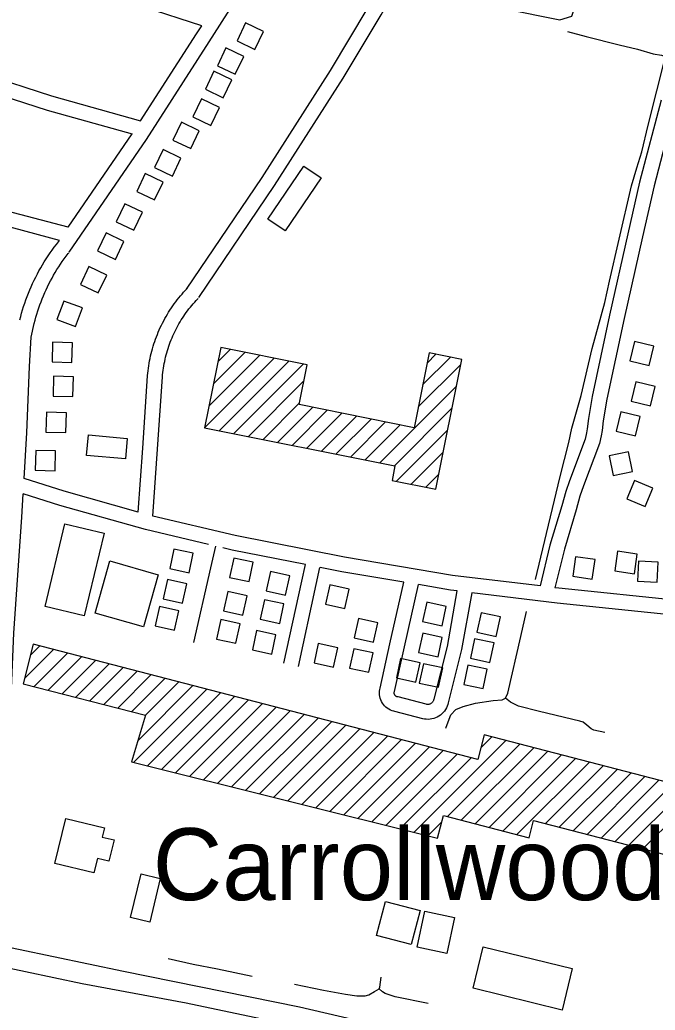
# Model space of a CAD drawing. Extents: x 3540316 to 3578335, y 553172 to 578787.
# Drawn here: x 3545660 to 3546942, y 572760 to 574758 of the extents above; entities that cross this region are included whole.
import ezdxf

# ---------------------------------------------------------------- set-up
doc = ezdxf.new("R2010")
doc.units = 0
for name, color, linetype in [('V-BLDG-OTLN', 7, 'Continuous'), ('V-ROAD-CNTR', 7, 'Continuous'), ('V-TOPO-GNAM-IDEN', 7, 'Continuous'), ('V-TOPO-SHOR', 7, 'Continuous')]:
    doc.layers.add(name, color=color, linetype=linetype)

msp = doc.modelspace()

# ---------------------------------------------------------------- linework, layer by layer
at = {"layer": 'V-BLDG-OTLN'}
for p, q in [((3546042, 573979.6), (3546144.2, 574081.8)), ((3546050.9, 574023.9), (3546114.7, 574087.7)), ((3546059.8, 574068.1), (3546085.3, 574093.6)), ((3546481.9, 574066), (3546499.5, 574083.6)), ((3546033.1, 573935.4), (3546173.6, 574075.9)), ((3546062.6, 573929.5), (3546203.1, 574070)), ((3546092, 573923.6), (3546232.5, 574064.1)), ((3546464.2, 573977.5), (3546549.8, 574063.1)), ((3546473, 574021.8), (3546528.9, 574077.6)), ((3546121.5, 573917.7), (3546233.6, 574029.8)), ((3546386.5, 573864.5), (3546540.9, 574018.9)), ((3546150.9, 573911.8), (3546224.7, 573985.5)), ((3546180.4, 573905.9), (3546251, 573976.5)), ((3546209.8, 573899.9), (3546280.5, 573970.6)), ((3546239.3, 573894), (3546309.9, 573964.7)), ((3546415.9, 573858.6), (3546532, 573974.7)), ((3546268.7, 573888.1), (3546339.4, 573958.8)), ((3546298.1, 573882.2), (3546368.8, 573952.9)), ((3546327.6, 573876.3), (3546398.3, 573947)), ((3546357, 573870.4), (3546427.7, 573941.1)), ((3546420.2, 573827.5), (3546523.1, 573930.4)), ((3546449.7, 573821.6), (3546514.3, 573886.2)), ((3546479.1, 573815.7), (3546505.4, 573842)), ((3545670, 573429.6), (3545728.4, 573488)), ((3545681.9, 573476.9), (3545700.3, 573495.3)), ((3545689.2, 573413.5), (3545756.4, 573480.7)), ((3545717.3, 573406.2), (3545784.5, 573473.5)), ((3545745.4, 573398.9), (3545812.6, 573466.2)), ((3545773.4, 573391.7), (3545840.7, 573458.9)), ((3545801.5, 573384.4), (3545868.8, 573451.6)), ((3545829.6, 573377.1), (3545896.9, 573444.4)), ((3545857.7, 573369.8), (3545924.9, 573437.1)), ((3545885.8, 573362.6), (3545953, 573429.8)), ((3545913.9, 573355.3), (3545981.1, 573422.6)), ((3545889.5, 573260.2), (3546037.3, 573408)), ((3545898.7, 573304.8), (3546009.2, 573415.3)), ((3545917.8, 573253.1), (3546065.4, 573400.7)), ((3545946.1, 573246.1), (3546093.4, 573393.5)), ((3545974.4, 573239), (3546121.5, 573386.2)), ((3546002.7, 573232), (3546149.6, 573378.9)), ((3546030.9, 573224.9), (3546177.7, 573371.7)), ((3546059.2, 573217.8), (3546205.8, 573364.4)), ((3546087.5, 573210.8), (3546233.9, 573357.1)), ((3546115.8, 573203.7), (3546261.9, 573349.8)), ((3546144.1, 573196.7), (3546290, 573342.6)), ((3546172.4, 573189.6), (3546318.1, 573335.3)), ((3546200.7, 573182.6), (3546346.2, 573328)), ((3546229, 573175.5), (3546374.3, 573320.7)), ((3546257.3, 573168.4), (3546402.4, 573313.5)), ((3546285.6, 573161.4), (3546430.4, 573306.2)), ((3546455.4, 573119), (3546640.8, 573304.4)), ((3546590.7, 573289.7), (3546612.7, 573311.7)), ((3546313.9, 573154.3), (3546458.5, 573298.9)), ((3546342.2, 573147.3), (3546486.6, 573291.7)), ((3546370.5, 573140.2), (3546514.7, 573284.4)), ((3546522.8, 573151.1), (3546668.9, 573297.2)), ((3546550.9, 573143.8), (3546697, 573289.9)), ((3546579, 573136.5), (3546725.1, 573282.6)), ((3546398.8, 573133.1), (3546542.8, 573277.1)), ((3546427.1, 573126.1), (3546570.9, 573269.8)), ((3546607.1, 573129.3), (3546753.1, 573275.3)), ((3546635.2, 573122), (3546781.2, 573268.1)), ((3546663.3, 573114.8), (3546809.3, 573260.8)), ((3546720.5, 573136.7), (3546837.4, 573253.5)), ((3546748.6, 573129.4), (3546865.5, 573246.3)), ((3546776.7, 573122.1), (3546893.5, 573239)), ((3546804.8, 573114.9), (3546921.6, 573231.7)), ((3546832.9, 573107.6), (3546949.7, 573224.4)), ((3546861, 573100.3), (3546977.8, 573217.2)), ((3546889.1, 573093.1), (3547007, 573211.1)), ((3546917.2, 573085.8), (3547035.1, 573203.8)), ((3546483.7, 573112), (3546511.3, 573139.6))]:
    msp.add_line(p, q, dxfattribs=at)
for points in [[(3546115.9, 574752), (3546098.6, 574715.9), (3546134.7, 574698.6), (3546152, 574734.7)], [(3546076.1, 574701.9), (3546058.8, 574665.8), (3546094.9, 574648.5), (3546112.2, 574684.6)], [(3546052, 574654.5), (3546034.7, 574618.4), (3546070.8, 574601.1), (3546088.1, 574637.2)], [(3546026.7, 574598.8), (3546009.4, 574562.7), (3546045.5, 574545.4), (3546062.8, 574581.5)], [(3545986.3, 574551.8), (3545969.1, 574515.8), (3546005.1, 574498.5), (3546022.4, 574534.6)], [(3545949.3, 574496.4), (3545932, 574460.4), (3545968.1, 574443.1), (3545985.4, 574479.2)], [(3546160.9, 574356.5), (3546233.4, 574463), (3546268.1, 574439.4), (3546195.6, 574332.9)], [(3545913.2, 574448.3), (3545896, 574412.2), (3545932, 574394.9), (3545949.3, 574431)], [(3545871.8, 574387.2), (3545854.6, 574351.1), (3545890.6, 574333.9), (3545907.9, 574370)], [(3545834.3, 574328.4), (3545817.1, 574292.3), (3545853.1, 574275), (3545870.4, 574311.1)], [(3545799.8, 574260.7), (3545782.6, 574224.6), (3545818.6, 574207.4), (3545835.9, 574243.5)], [(3545735, 574153.5), (3545772.6, 574139.6), (3545786.4, 574177.1), (3545748.9, 574191)], [(3545726.3, 574108), (3545725.3, 574068.1), (3545765.3, 574067), (3545766.3, 574107)], [(3546900.2, 574109.4), (3546890.8, 574070.6), (3546929.7, 574061.2), (3546939.1, 574100)], [(3546033.1, 573935.4), (3546417.2, 573858.3), (3546411.4, 573829.3), (3546499.3, 573811.6), (3546551.8, 574073.1), (3546486, 574086.3), (3546455.7, 573935.5), (3546224, 573982), (3546240.1, 574062.5), (3546065.7, 574097.6)], [(3545728.4, 574039.2), (3545727.4, 573999.2), (3545767.4, 573998.2), (3545768.4, 574038.2)], [(3546903.2, 574028.2), (3546893.8, 573989.3), (3546932.7, 573979.9), (3546942.1, 574018.8)], [(3545714.1, 573966.7), (3545713, 573926.7), (3545753, 573925.7), (3545754.1, 573965.7)], [(3546872.7, 573967.3), (3546863.3, 573928.5), (3546902.2, 573919), (3546911.6, 573957.9)], [(3545798.6, 573920.8), (3545877.1, 573913.9), (3545873.4, 573872.4), (3545794.9, 573879.4)], [(3545692.4, 573889.5), (3545691.4, 573849.5), (3545731.4, 573848.5), (3545732.4, 573888.5)], [(3546896.6, 573847.4), (3546888.6, 573886.5), (3546849.4, 573878.5), (3546857.5, 573839.3)], [(3546885, 573791.7), (3546922, 573776.6), (3546937.1, 573813.6), (3546900.1, 573828.7)], [(3545711.4, 573574.9), (3545751.2, 573741.3), (3545830.1, 573722.4), (3545790.2, 573556)], [(3545962.7, 573651.5), (3546001.8, 573643), (3546010.3, 573682.1), (3545971.3, 573690.6)], [(3546900.1, 573640.8), (3546905.8, 573680.4), (3546866.2, 573686.1), (3546860.5, 573646.5)], [(3545812.2, 573561.5), (3545842, 573666.6), (3545939.4, 573638.9), (3545909.5, 573533.8)], [(3546083.6, 573633.4), (3546122.7, 573624.9), (3546131.2, 573664), (3546092.1, 573672.5)], [(3546815.3, 573630), (3546821, 573669.6), (3546781.4, 573675.3), (3546775.7, 573635.8)], [(3546948.3, 573664), (3546908.4, 573666.2), (3546906.2, 573626.2), (3546946.1, 573624.1)], [(3546157.4, 573606.1), (3546196.5, 573597.6), (3546205.1, 573636.6), (3546166, 573645.2)], [(3545949.5, 573590.2), (3545988.6, 573581.7), (3545997.2, 573620.8), (3545958.1, 573629.3)], [(3546071.1, 573566), (3546110.1, 573557.5), (3546118.7, 573596.5), (3546079.6, 573605.1)], [(3546276.9, 573579.5), (3546315.9, 573570.9), (3546324.5, 573610), (3546285.4, 573618.5)], [(3546145.5, 573549.4), (3546184.6, 573540.8), (3546193.1, 573579.9), (3546154.1, 573588.4)], [(3546473, 573544.5), (3546512.1, 573535.9), (3546520.6, 573575), (3546481.5, 573583.5)], [(3545933.6, 573535.8), (3545972.6, 573527.2), (3545981.2, 573566.3), (3545942.1, 573574.9)], [(3546582.5, 573523.2), (3546621.5, 573514.6), (3546630.1, 573553.7), (3546591, 573562.3)], [(3546057.3, 573509.2), (3546096.3, 573500.7), (3546104.9, 573539.7), (3546065.8, 573548.3)], [(3546335, 573511.6), (3546374.1, 573503), (3546382.6, 573542.1), (3546343.6, 573550.7)], [(3546129.4, 573487.2), (3546168.5, 573478.6), (3546177.1, 573517.7), (3546138, 573526.3)], [(3546464.9, 573481.7), (3546504, 573473.1), (3546512.5, 573512.2), (3546473.5, 573520.7)], [(3546569.4, 573470.7), (3546608.5, 573462.1), (3546617, 573501.2), (3546577.9, 573509.8)], [(3545913.9, 573355.3), (3545885.6, 573261.2), (3546502.9, 573107.2), (3546514.8, 573153.1), (3546687.6, 573108.4), (3546696.5, 573142.8), (3546961.5, 573074.4), (3546964.1, 573084.5), (3547101.8, 573048.9), (3547135.2, 573177.9), (3546988.7, 573215.8), (3546988.3, 573214.4), (3546597.4, 573315.7), (3546584.6, 573266.3), (3545687.4, 573498.6), (3545667.3, 573419.1)], [(3546253.9, 573460.9), (3546293, 573452.3), (3546301.6, 573491.4), (3546262.5, 573500)], [(3546325.6, 573450.6), (3546364.7, 573442.1), (3546373.2, 573481.1), (3546334.1, 573489.7)], [(3546420.1, 573430.9), (3546459.2, 573422.4), (3546467.7, 573461.4), (3546428.6, 573470)], [(3546465.9, 573420.4), (3546505, 573411.8), (3546513.5, 573450.9), (3546474.4, 573459.4)], [(3546555.8, 573417.6), (3546594.9, 573409.1), (3546603.4, 573448.1), (3546564.3, 573456.7)], [(3545730.8, 573056.5), (3545753, 573147.3), (3545831.1, 573128.3), (3545826.6, 573109.7), (3545850.4, 573103.9), (3545839.9, 573061), (3545816.9, 573066.7), (3545809.7, 573037.3)], [(3545883.6, 572947.1), (3545905.1, 573035.7), (3545943.7, 573026.4), (3545922.3, 572937.7)], [(3546380, 572911.2), (3546397.8, 572979.5), (3546467.9, 572961.2), (3546450.1, 572892.9)], [(3546462, 572887.5), (3546477.4, 572960), (3546537.1, 572947.4), (3546521.7, 572874.8)], [(3546754.3, 572760.8), (3546574.8, 572804.7), (3546595.3, 572888.5), (3546774.8, 572844.6)]]:
    msp.add_lwpolyline(points, close=True, dxfattribs=at)
at = {"layer": 'V-ROAD-CNTR'}
for points in [[(3545759.7, 574289.4), (3545915.7, 574517.1), (3546042.3, 574713.7), (3546138, 574864.1), (3546178.1, 574938.5), (3546219.3, 575018.4), (3546255.3, 575105.5), (3546294.3, 575222.7), (3546322.5, 575318.5), (3546343.7, 575424.3), (3546366.2, 575533.1)], [(3546027.4, 574746.2), (3545911.1, 574783.8), (3545662.4, 574859.3), (3545540.2, 574894.9), (3545502.6, 574905.8), (3545484.1, 574903), (3545368.1, 574867.6), (3545097.4, 574794.7), (3544965.5, 574757.9)], [(3545996.3, 574214.7), (3546149, 574440.5), (3546287.4, 574656.2), (3546363.2, 574783.5), (3546415, 574874.7), (3546646.7, 574810), (3546748.4, 574789.5), (3546750.4, 574790.1), (3546754.2, 574801.8), (3546764.3, 574848.2)], [(3546021.2, 574197.9), (3546174.1, 574424), (3546312.9, 574640.4), (3546389.2, 574768.4), (3546429.6, 574839.5), (3546639.7, 574780.8), (3546749.5, 574758.6), (3546774, 574765.5), (3546783.2, 574794), (3546793.6, 574841.9)], [(3545904, 574554.4), (3546017, 574729.9), (3546027.4, 574746.2)], [(3545586.8, 574649.1), (3545724.2, 574604.9), (3545904, 574554.4)], [(3545577.7, 574620.5), (3545715.5, 574576.2), (3545886.8, 574528.1)], [(3546954.2, 574596.2), (3546910.6, 574430.5), (3546887.3, 574326.8), (3546850, 574162.5), (3546815.3, 573998.7), (3546807.4, 573953.8), (3546805.2, 573933.5), (3546803.9, 573924.9), (3546800.8, 573912.6), (3546769.6, 573828.5), (3546761.6, 573806.5), (3546753.8, 573777.9), (3546729.9, 573698.4), (3546709.8, 573616.2)], [(3546983.3, 574588.8), (3546939.8, 574423.4), (3546916.6, 574320.2), (3546879.3, 574156.1), (3546844.7, 573993), (3546837.1, 573949.5), (3546834.9, 573929.7), (3546833.4, 573919), (3546829.5, 573903.7), (3546797.7, 573818.2), (3546790.3, 573797.5), (3546782.7, 573769.6), (3546758.9, 573690.5), (3546739.8, 573612.6)], [(3545757.8, 574339.7), (3545886.8, 574528.1)], [(3545740.4, 574313.3), (3545597.6, 574351.2), (3545331.5, 574432.5), (3545126.4, 574494)], [(3545757.8, 574339.7), (3545605.8, 574380), (3545340.2, 574461.3), (3545245.1, 574489.7)], [(3545660.3, 574152.9), (3545662, 574159.7), (3545663.9, 574166.6), (3545665.9, 574173.4), (3545668, 574180.2), (3545670.2, 574187), (3545672.6, 574193.6), (3545675, 574200.3), (3545677.6, 574206.9), (3545680.3, 574213.5), (3545683.2, 574220), (3545686.1, 574226.5), (3545689.1, 574232.9), (3545692.3, 574239.3), (3545695.6, 574245.6), (3545698.9, 574251.8), (3545702.4, 574258), (3545706, 574264.2), (3545709.7, 574270.3), (3545713.5, 574276.3), (3545717.4, 574282.2), (3545721.4, 574288.1), (3545725.5, 574293.9), (3545729.7, 574299.6), (3545734, 574305.2), (3545740.4, 574313.3)], [(3545689.4, 574145.6), (3545691, 574152.1), (3545692.7, 574158.3), (3545694.6, 574164.7), (3545696.6, 574171), (3545698.6, 574177.2), (3545700.8, 574183.5), (3545703.1, 574189.7), (3545705.5, 574195.7), (3545708, 574201.8), (3545710.6, 574207.9), (3545713.3, 574213.9), (3545716.1, 574219.9), (3545719, 574225.7), (3545722.1, 574231.6), (3545725.2, 574237.4), (3545728.4, 574243.1), (3545731.8, 574248.8), (3545735.2, 574254.4), (3545738.7, 574260), (3545742.3, 574265.5), (3545746, 574271), (3545749.8, 574276.3), (3545753.7, 574281.6), (3545757.7, 574286.9), (3545759.1, 574288.5)], [(3545918, 574040.5), (3545918.5, 574045.5), (3545919, 574050.5), (3545919.7, 574055.4), (3545920.4, 574060.5), (3545921.2, 574065.5), (3545922.1, 574070.4), (3545923.1, 574075.3), (3545924.2, 574080.3), (3545925.4, 574085.2), (3545926.6, 574090.1), (3545928, 574094.9), (3545929.4, 574099.8), (3545930.9, 574104.7), (3545932.5, 574109.4), (3545934.2, 574114.2), (3545935.9, 574118.9), (3545937.7, 574123.6), (3545939.7, 574128.3), (3545941.7, 574133), (3545943.7, 574137.5), (3545945.9, 574142.1), (3545948.2, 574146.6), (3545950.5, 574151.1), (3545952.9, 574155.5), (3545955.4, 574159.9), (3545957.9, 574164.3), (3545960.5, 574168.6), (3545963.2, 574172.9), (3545966, 574177.1), (3545968.9, 574181.3), (3545971.8, 574185.4), (3545974.8, 574189.5), (3545977.8, 574193.5), (3545981, 574197.4), (3545984.1, 574201.3), (3545987.5, 574205.2), (3545990.8, 574209), (3545994.2, 574212.7), (3545997.6, 574216.4), (3545998.8, 574217.6)], [(3545947.9, 574037.8), (3545948.3, 574042.4), (3545948.8, 574046.8), (3545949.4, 574051.4), (3545950, 574055.9), (3545950.8, 574060.3), (3545951.6, 574064.8), (3545952.5, 574069.2), (3545953.4, 574073.6), (3545954.5, 574078), (3545955.6, 574082.4), (3545956.8, 574086.8), (3545958.1, 574091.1), (3545959.4, 574095.4), (3545960.9, 574099.7), (3545962.4, 574104), (3545963.9, 574108.2), (3545965.6, 574112.5), (3545967.3, 574116.6), (3545969.1, 574120.8), (3545971, 574124.9), (3545972.9, 574129), (3545974.9, 574133), (3545977, 574137.1), (3545979.1, 574141.1), (3545981.4, 574145), (3545983.7, 574148.9), (3545986, 574152.8), (3545988.4, 574156.6), (3545990.9, 574160.4), (3545993.5, 574164.1), (3545996.1, 574167.8), (3545998.8, 574171.5), (3546001.5, 574175), (3546004.4, 574178.6), (3546007.2, 574182.1), (3546010.1, 574185.5), (3546013.1, 574189), (3546016.2, 574192.3), (3546019.3, 574195.6), (3546020.3, 574196.7)], [(3545668.9, 573833.3), (3545674.5, 573925), (3545679.9, 574058.7), (3545683.4, 574118), (3545689.5, 574146)], [(3545899.2, 573765.1), (3545908.4, 573894.5), (3545918, 574040.2)], [(3545928.7, 573757.1), (3545938.3, 573892.5), (3545947.9, 574038.2)], [(3545899.2, 573765.1), (3545749.7, 573807.2), (3545668.9, 573833.3)], [(3545617.9, 572894.5), (3545620.5, 572961.8), (3545635.9, 573234.3), (3545648.5, 573521.3), (3545664.1, 573754.8), (3545667, 573802.4)], [(3546041.2, 573699.8), (3545913.8, 573729.8), (3545741.1, 573778.5), (3545667, 573802.4)], [(3546710, 573616.2), (3546533.4, 573637.6), (3546315.4, 573674.5), (3546094.8, 573718), (3545928.7, 573757.1)], [(3546011.4, 573502.3), (3546045.9, 573652.7), (3546055.5, 573696.4)], [(3546236.4, 573659.5), (3546088.5, 573688.6), (3546069.8, 573693)], [(3546193.2, 573460.3), (3546229.1, 573625.9), (3546236.3, 573659.5)], [(3546222.5, 573453.9), (3546258.4, 573619.5), (3546265.8, 573653.7)], [(3546435.1, 573623.8), (3546310, 573645), (3546265.9, 573653.7)], [(3546572.1, 573602.7), (3546551.5, 573487.9), (3546524.7, 573380.5), (3546523.9, 573377.4), (3546522.6, 573373.8), (3546521.1, 573370.4), (3546519.2, 573367), (3546517, 573363.9), (3546514.6, 573361), (3546511.9, 573358.3), (3546509, 573355.8), (3546505.8, 573353.7), (3546502.5, 573351.8), (3546499.1, 573350.2), (3546495.5, 573348.9), (3546491.8, 573348), (3546488, 573347.4), (3546484.3, 573347.1), (3546480.4, 573347.2), (3546476.7, 573347.6), (3546473.1, 573348.3), (3546417, 573363), (3546414.6, 573363.5), (3546411.2, 573364.5), (3546407.8, 573365.8), (3546404.6, 573367.5), (3546401.6, 573369.4), (3546398.7, 573371.7), (3546396.1, 573374.2), (3546393.8, 573376.9), (3546391.7, 573379.8), (3546389.9, 573383), (3546388.4, 573386.2), (3546387.2, 573389.7), (3546386.3, 573393.2), (3546385.8, 573396.7), (3546385.6, 573400.4), (3546385.8, 573404), (3546386.3, 573407.5), (3546387, 573410.2), (3546406.9, 573499.7), (3546434.7, 573623.9)], [(3546542.2, 573606.4), (3546522.2, 573494.2), (3546495.6, 573387.8), (3546495.1, 573386.1), (3546494.8, 573385), (3546494.3, 573384), (3546493.8, 573383), (3546493.1, 573382.1), (3546492.4, 573381.2), (3546491.6, 573380.4), (3546490.7, 573379.7), (3546489.8, 573379.1), (3546488.8, 573378.5), (3546487.8, 573378), (3546486.7, 573377.7), (3546485.7, 573377.4), (3546484.5, 573377.2), (3546483.4, 573377.1), (3546482.3, 573377.1), (3546481.2, 573377.3), (3546479.9, 573377.5), (3546423.7, 573392.3), (3546421.7, 573392.6), (3546421, 573392.9), (3546420.3, 573393.1), (3546419.6, 573393.5), (3546419, 573393.9), (3546418.4, 573394.4), (3546417.9, 573394.9), (3546417.4, 573395.5), (3546416.9, 573396.1), (3546416.6, 573396.7), (3546416.2, 573397.4), (3546416, 573398.1), (3546415.8, 573398.9), (3546415.7, 573399.6), (3546415.7, 573400.4), (3546415.7, 573401.1), (3546415.8, 573401.9), (3546416.2, 573403.4), (3546436.2, 573493.1), (3546464.3, 573618.9)], [(3546542.8, 573606.3), (3546529.1, 573608), (3546464.4, 573618.9)], [(3547316, 573538.2), (3547267.9, 573538.9), (3546992, 573556.3), (3546744.5, 573581.8), (3546572.5, 573602.7)], [(3547312.6, 573568.2), (3547269, 573568.8), (3546994.5, 573586.2), (3546747.8, 573611.6), (3546739.7, 573612.6)], [(3544410.8, 573132.1), (3544728.4, 573069.5), (3545100.5, 572993.8), (3545515.6, 572913.3), (3545869.3, 572839.3), (3546224.2, 572767), (3546505.2, 572702.3)], [(3546286.1, 572713.1), (3545996.1, 572774.7), (3545786.3, 572813.7), (3545556.4, 572862.1), (3545264, 572922.9), (3544953.3, 572984.2), (3544669.5, 573041.9), (3544411.1, 573094.2)]]:
    msp.add_lwpolyline(points, dxfattribs=at)
at = {"layer": 'V-TOPO-SHOR'}
for points in [[(3546765.1, 574734.9), (3546803.1, 574724.4), (3546869.4, 574708.1), (3546906.8, 574699), (3546937.9, 574689.8), (3546955.1, 574687), (3546962.7, 574684.1)], [(3546701, 573629.5), (3546711.6, 573674.4), (3546750.3, 573837.1), (3546767.9, 573905.4), (3546774.2, 573934.4), (3546792.5, 574000.6), (3546815, 574095.1), (3546840.3, 574188.2), (3546850.2, 574230.9), (3546869.2, 574315.8), (3546894.5, 574423.4), (3546905.1, 574459.9), (3546914.9, 574492.3), (3546928.2, 574546.1), (3546962.7, 574684.1)], [(3546520.1, 573329.3), (3546526.4, 573347.2), (3546529.9, 573356.2), (3546539.7, 573367.2), (3546554.9, 573373.3), (3546579.8, 573380.1), (3546615, 573385.5), (3546633.6, 573386.8), (3546639.9, 573390.2), (3546644.8, 573399.9), (3546670.8, 573514.4), (3546682.8, 573564.7)], [(3546840.5, 573320.9), (3546818.4, 573325.2), (3546812.9, 573328), (3546804, 573335.6), (3546797.1, 573341.2), (3546790.2, 573343.3), (3546708.8, 573363), (3546666.7, 573373.5), (3546650.2, 573381.9), (3546639.9, 573390.2)], [(3545959.7, 572864.5), (3546010.2, 572853.2), (3546059.3, 572844), (3546129.1, 572829.1)], [(3546214.2, 572812.8), (3546273, 572800.8), (3546317.3, 572792.9), (3546340.1, 572789.4), (3546356.7, 572789.3), (3546364.4, 572791.3), (3546376.1, 572798.2), (3546385.2, 572803.7), (3546386.6, 572807.2), (3546389.4, 572827.2)], [(3546484, 572774.2), (3546417.6, 572787.6), (3546397.6, 572794), (3546392.1, 572797.5), (3546385.2, 572803.7)]]:
    msp.add_lwpolyline(points, dxfattribs=at)

# ---------------------------------------------------------------- texts
at = {"layer": 'V-TOPO-GNAM-IDEN'}
msp.add_text('Carrollwood', height=145, dxfattribs=at).set_placement((3545928.6, 572982.5))

doc.saveas('drawing.dxf')
